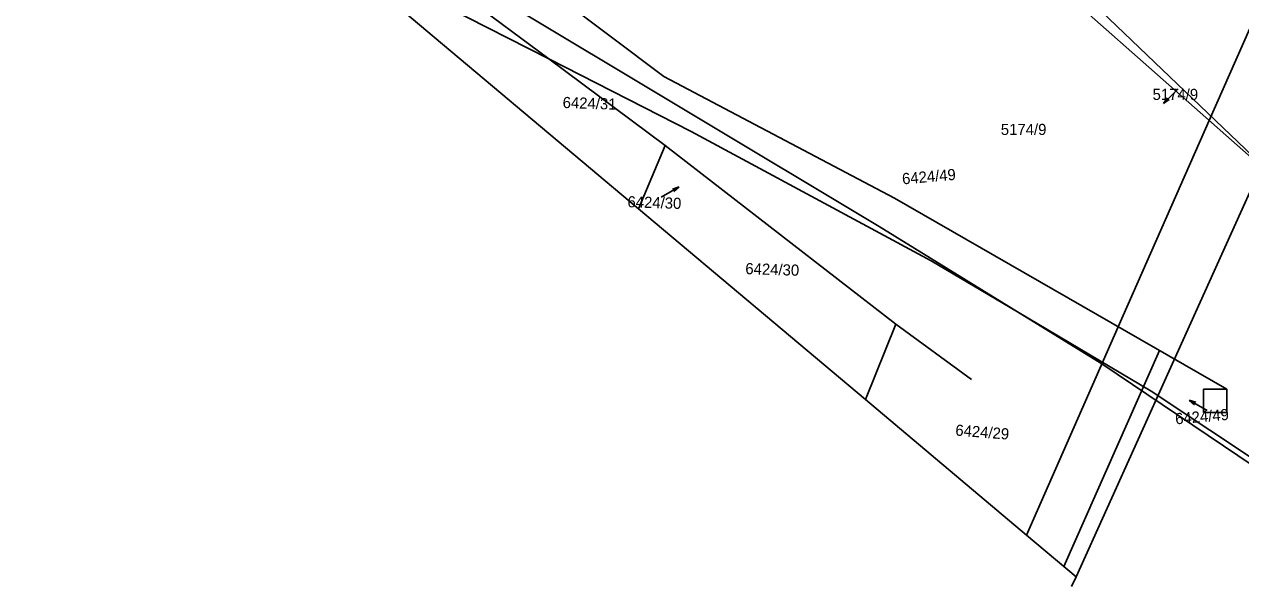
# Model space of a CAD drawing. Extents: x -400488 to -400124, y -1251493 to -1251223.
# Drawn here: x -400483.5 to -400431, y -1251492.8 to -1251468.6 of the extents above; entities that cross this region are included whole.
import ezdxf

# ---------------------------------------------------------------- set-up
doc = ezdxf.new("R2010")
doc.units = 0
doc.layers.add('Level 63', color=7, linetype='Continuous')

msp = doc.modelspace()

# ---------------------------------------------------------------- linework, layer by layer
at = {"layer": 'Level 63'}
for p, q in [((-400455.9, -1251470.84), (-400483.46, -1251450.05)), ((-400483.46, -1251450.05), (-400455.9, -1251470.84)), ((-400470.59, -1251462.92), (-400446.62, -1251477.3)), ((-400446.62, -1251477.3), (-400470.59, -1251462.92)), ((-400460.85, -1251470.08), (-400468.27, -1251464.56)), ((-400468.27, -1251464.56), (-400460.85, -1251470.08)), ((-400432.39, -1251472.74), (-400428.83, -1251464.68)), ((-400432.39, -1251472.74), (-400428.83, -1251464.68)), ((-400439.63, -1251465.54), (-400428.8, -1251475.91)), ((-400428.8, -1251475.91), (-400439.63, -1251465.54)), ((-400428.8, -1251475.91), (-400439.88, -1251466.11)), ((-400439.88, -1251466.11), (-400428.8, -1251475.91)), ((-400469.04, -1251466.41), (-400456.99, -1251476.54)), ((-400456.99, -1251476.54), (-400469.04, -1251466.41)), ((-400456.99, -1251476.54), (-400469.04, -1251466.41)), ((-400466.95, -1251466.97), (-400460.85, -1251470.08)), ((-400460.85, -1251470.08), (-400454.72, -1251473.21)), ((-400455.84, -1251473.81), (-400460.85, -1251470.08)), ((-400460.85, -1251470.08), (-400455.84, -1251473.81)), ((-400445.96, -1251476.08), (-400455.9, -1251470.84)), ((-400455.9, -1251470.84), (-400445.96, -1251476.08)), ((-400433.73, -1251471.37), (-400434.366, -1251472.007)), ((-400434.196, -1251471.752), (-400434.366, -1251472.007)), ((-400434.366, -1251472.007), (-400434.112, -1251471.837)), ((-400436.31, -1251481.62), (-400432.39, -1251472.74)), ((-400436.31, -1251481.62), (-400432.39, -1251472.74)), ((-400454.72, -1251473.21), (-400444.37, -1251478.78)), ((-400456.99, -1251476.54), (-400455.84, -1251473.81)), ((-400455.84, -1251473.81), (-400456.99, -1251476.54)), ((-400455.84, -1251473.81), (-400445.89, -1251481.51)), ((-400445.89, -1251481.51), (-400455.84, -1251473.81)), ((-400438.13, -1251492.39), (-400430.11, -1251474.65)), ((-400456.01, -1251476.04), (-400455.23, -1251475.59)), ((-400455.23, -1251475.59), (-400455.52, -1251475.688)), ((-400455.46, -1251475.792), (-400455.23, -1251475.59)), ((-400431.63, -1251484.31), (-400445.96, -1251476.08)), ((-400445.96, -1251476.08), (-400431.63, -1251484.31)), ((-400456.99, -1251476.54), (-400447.21, -1251484.76)), ((-400447.21, -1251484.76), (-400456.99, -1251476.54)), ((-400447.21, -1251484.76), (-400456.99, -1251476.54)), ((-400446.62, -1251477.3), (-400440.65, -1251480.98)), ((-400440.65, -1251480.98), (-400446.62, -1251477.3)), ((-400444.37, -1251478.78), (-400440.65, -1251480.98)), ((-400440.65, -1251480.98), (-400434.89, -1251484.39)), ((-400440.65, -1251480.98), (-400437.02, -1251483.22)), ((-400437.02, -1251483.22), (-400440.65, -1251480.98)), ((-400447.21, -1251484.76), (-400445.89, -1251481.51)), ((-400445.89, -1251481.51), (-400447.21, -1251484.76)), ((-400445.89, -1251481.51), (-400442.63, -1251483.89)), ((-400442.63, -1251483.89), (-400445.89, -1251481.51)), ((-400440.26, -1251490.6), (-400436.31, -1251481.62)), ((-400440.26, -1251490.6), (-400436.31, -1251481.62)), ((-400434.53, -1251482.64), (-400438.66, -1251491.95)), ((-400437.02, -1251483.22), (-400427.72, -1251489.49)), ((-400427.72, -1251489.49), (-400437.02, -1251483.22)), ((-400434.89, -1251484.39), (-400422.83, -1251492.43)), ((-400432.63, -1251485.31), (-400432.63, -1251484.31)), ((-400432.63, -1251484.31), (-400431.63, -1251484.31)), ((-400431.63, -1251484.31), (-400432.63, -1251484.31)), ((-400432.63, -1251484.31), (-400432.63, -1251485.31)), ((-400431.63, -1251484.31), (-400431.63, -1251485.31)), ((-400431.63, -1251485.31), (-400431.63, -1251484.31)), ((-400447.21, -1251484.76), (-400440.26, -1251490.6)), ((-400440.26, -1251490.6), (-400447.21, -1251484.76)), ((-400440.26, -1251490.6), (-400447.21, -1251484.76)), ((-400432.47, -1251485.23), (-400433.249, -1251484.78)), ((-400433.249, -1251484.78), (-400433.019, -1251484.982)), ((-400432.959, -1251484.878), (-400433.249, -1251484.78)), ((-400431.63, -1251485.31), (-400432.63, -1251485.31)), ((-400432.63, -1251485.31), (-400431.63, -1251485.31)), ((-400440.26, -1251490.6), (-400438.66, -1251491.95)), ((-400438.66, -1251491.95), (-400440.26, -1251490.6)), ((-400438.66, -1251491.95), (-400440.26, -1251490.6)), ((-400438.13, -1251492.39), (-400440.26, -1251490.6)), ((-400438.33, -1251492.82), (-400438.13, -1251492.39))]:
    msp.add_line(p, q, dxfattribs=at)

# ---------------------------------------------------------------- texts
for p in [(-400434.83, -1251471.85), (-400441.37, -1251473.36)]:
    msp.add_text('5174/9', height=0.48, dxfattribs=at).set_placement(p)
for s, rotation, p in [('6424/31', 358.1, (-400460.263, -1251472.195)), ('6424/49', 4.91, (-400445.606, -1251475.489)), ('6424/30', 358.1, (-400457.469, -1251476.472)), ('6424/30', 358.1, (-400452.389, -1251479.352)), ('6424/49', 4.91, (-400433.836, -1251485.829)), ('6424/29', 355.55, (-400443.345, -1251486.307))]:
    msp.add_text(s, height=0.48, rotation=rotation, dxfattribs=at).set_placement(p)

doc.saveas('drawing.dxf')
